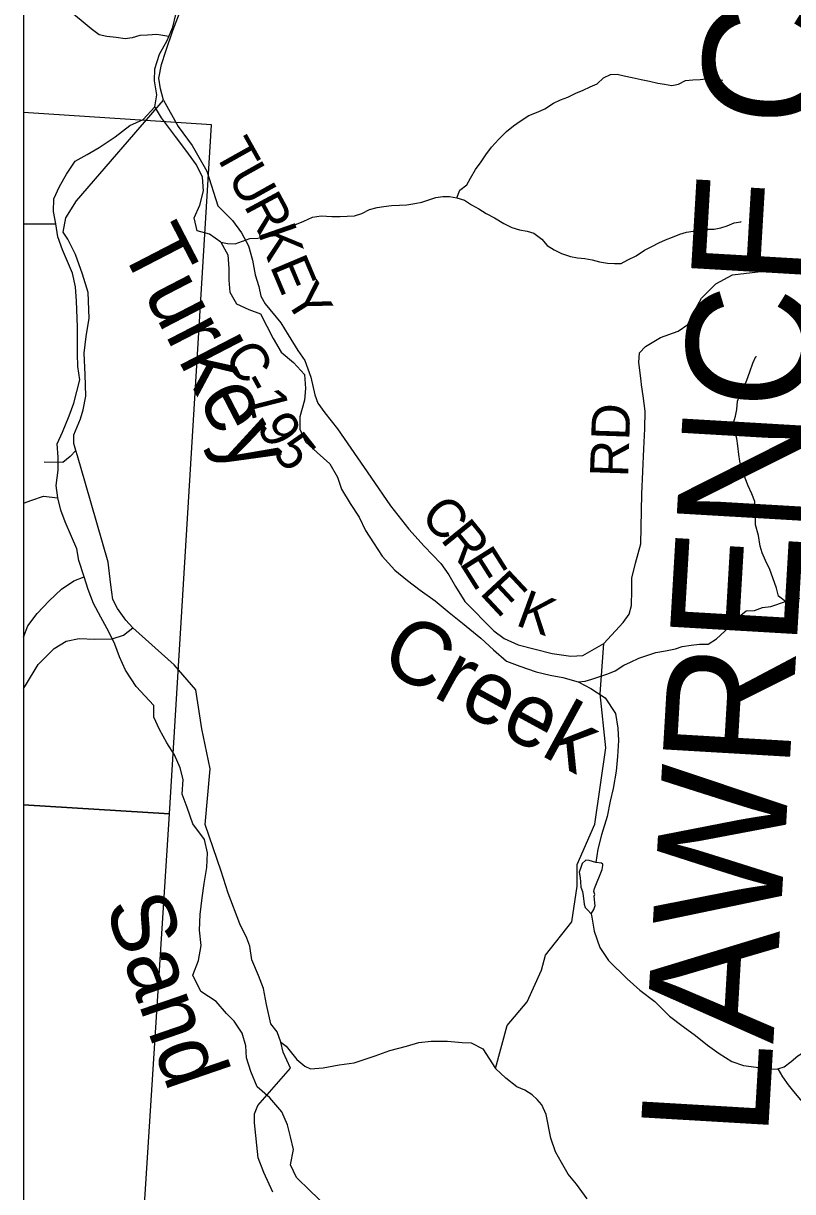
# Model space of a CAD drawing. Extents: x 396.2 to 468.4, y 232.6 to 279.1.
# Drawn here: x 413.851 to 414.996, y 268.036 to 269.775 of the extents above; entities that cross this region are included whole.
import ezdxf

# ---------------------------------------------------------------- set-up
doc = ezdxf.new("R2010")
doc.units = 0
for name, color, linetype in [('Default', 7, 'Continuous'), ('GM_X_County_Road', 7, 'Continuous'), ('GM_X_County_Road_Text', 7, 'Continuous'), ('GM_X_County_Text', 7, 'Continuous'), ('GM_X_Minor_Lake', 7, 'Continuous'), ('GM_X_Minor_River', 7, 'Continuous'), ('GM_X_Minor_River_Text', 7, 'Continuous'), ('GM_X_Township_Road', 7, 'Continuous'), ('SH_Cut_Line', 7, 'Continuous'), ('TX_P_1', 7, 'Continuous')]:
    doc.layers.add(name, color=color, linetype=linetype)

msp = doc.modelspace()

# ---------------------------------------------------------------- linework, layer by layer
at = {"layer": 'Default'}
for points in [[(413.8513, 270.6726), (413.8513, 264.4868), (414.0592, 264.474), (414.3542, 264.4559), (414.8754, 264.4239), (414.9163, 265.108), (414.9927, 266.2714), (414.9935, 266.2891), (414.9982, 266.4735), (415.0293, 266.9964), (415.0582, 267.4588), (415.0934, 268.0402), (415.1765, 269.4523), (415.2459, 270.5284), (415.2492, 270.5871), (414.466, 270.6401), (414.1359, 270.6553), (413.8849, 270.6706)], [(413.8513, 269.6425), (413.8513, 268.6118), (414.0685, 268.5986), (414.131, 269.6239)], [(413.8513, 268.6118), (413.8513, 267.5757), (414.0029, 267.5669), (414.0685, 268.5986)]]:
    msp.add_lwpolyline(points, close=True, dxfattribs=at)
at = {"layer": 'GM_X_County_Road'}
for points in [[(414.0141, 268.8752), (414.0038, 268.8869), (413.9915, 268.9039), (413.9846, 268.9176), (413.9815, 268.9392), (413.9775, 268.973), (413.9439, 269.0902), (413.9319, 269.1312), (413.9294, 269.1395), (413.9265, 269.1497), (413.9264, 269.1627), (413.9365, 269.1866), (413.9402, 269.1996), (413.9443, 269.2201), (413.9433, 269.2524), (413.9416, 269.2843), (413.9449, 269.309), (413.9493, 269.3363), (413.9475, 269.3743), (413.9394, 269.4016), (413.929, 269.4312), (413.9172, 269.4539), (413.9107, 269.4641), (413.9143, 269.4854), (413.9305, 269.5109), (414.06, 269.6608), (414.0553, 269.6775), (414.053, 269.6938), (414.057, 269.714), (414.0633, 269.7337), (414.0738, 269.7646), (414.0869, 269.7992)], [(414.06, 269.6608), (414.0818, 269.6215), (414.1023, 269.5931), (414.124, 269.5552), (414.1405, 269.5036), (414.1625, 269.4817), (414.1758, 269.4635), (414.1862, 269.4442), (414.192, 269.4226), (414.1962, 269.401), (414.2016, 269.3832), (414.2044, 269.3692), (414.2112, 269.3578), (414.2341, 269.3291), (414.2452, 269.3114), (414.2597, 269.2883), (414.2701, 269.2732), (414.2789, 269.2485), (414.2851, 269.222), (414.2893, 269.2095), (414.3, 269.1955), (414.3187, 269.1717), (414.3684, 269.0995), (414.3974, 269.0568), (414.4249, 269.0224), (414.4478, 268.9971), (414.4725, 268.9711), (414.4844, 268.9541), (414.4943, 268.937), (414.5081, 268.9147), (414.5511, 268.8709), (414.5664, 268.8596), (414.5876, 268.8499), (414.6378, 268.8369), (414.6658, 268.8329), (414.6836, 268.8341), (414.7149, 268.8518), (414.7437, 268.8834), (414.7527, 268.8956), (414.7561, 268.9086), (414.7563, 268.9313), (414.7566, 268.9492), (414.7618, 268.9716), (414.77, 269.0001), (414.7715, 269.0741), (414.7742, 269.1417), (414.7759, 269.1713), (414.7766, 269.1979), (414.7733, 269.2209)], [(414.7733, 269.2209), (414.7711, 269.237), (414.7703, 269.243), (414.7667, 269.2703), (414.7678, 269.2848), (414.7768, 269.2943), (414.7991, 269.3077), (414.8253, 269.317), (414.84, 269.3269), (414.849, 269.3452), (414.8603, 269.3662), (414.8814, 269.3872), (414.9063, 269.401), (415.0283, 269.4153), (415.0488, 269.4166), (415.0715, 269.4285), (415.0991, 269.4505), (415.1195, 269.4591), (415.1386, 269.4591), (415.1563, 269.4554), (415.1767, 269.4517)], [(414.2225, 268.0352), (414.2091, 268.0647), (414.2007, 268.0863), (414.1951, 268.1386), (414.195, 268.1519), (414.1999, 268.1641), (414.2489, 268.2196), (414.2377, 268.2434), (414.2344, 268.2586), (414.2291, 268.2738), (414.2197, 268.286), (414.2128, 268.3145), (414.2085, 268.3383), (414.2012, 268.3577), (414.1912, 268.3811), (414.1881, 268.4016), (414.1838, 268.4134), (414.1731, 268.4345), (414.1558, 268.4804), (414.1458, 268.5133), (414.1219, 268.5825), (414.1293, 268.6653), (414.1169, 268.7249), (414.1078, 268.783), (414.0758, 268.8204), (414.0141, 268.8752)]]:
    msp.add_lwpolyline(points, dxfattribs=at)
at = {"layer": 'GM_X_Minor_Lake'}
for points in [[(414.703, 268.5262), (414.6931, 268.5288), (414.6882, 268.5296), (414.6825, 268.5243), (414.681, 268.5201), (414.6784, 268.5114), (414.6795, 268.5031), (414.6802, 268.497), (414.6806, 268.4894), (414.6832, 268.4826), (414.6843, 268.4765), (414.6858, 268.4637), (414.687, 268.4591), (414.6907, 268.4553), (414.6962, 268.4495)], [(414.7122, 268.5156), (414.7134, 268.5213), (414.7134, 268.5237), (414.7113, 268.5249), (414.703, 268.5262)], [(414.6962, 268.4495), (414.7002, 268.4561), (414.7021, 268.4617), (414.7017, 268.4655), (414.701, 268.4716), (414.7006, 268.4758), (414.7014, 268.4784), (414.7002, 268.4826), (414.701, 268.4871), (414.7122, 268.5156)]]:
    msp.add_lwpolyline(points, dxfattribs=at)
at = {"layer": 'GM_X_Minor_River'}
msp.add_line((413.8997, 269.4762), (413.8513, 269.476), dxfattribs=at)
for points in [[(414.0679, 269.7558), (414.05, 269.7588), (414.0359, 269.7576), (414.0246, 269.7569), (414.0132, 269.7534), (414.0026, 269.7519), (413.9894, 269.7542), (413.9754, 269.7557), (413.964, 269.758), (413.9522, 269.7671), (413.9401, 269.7769), (413.9287, 269.7864), (413.9166, 269.7966), (413.9079, 269.8065), (413.8954, 269.8194), (413.8825, 269.8239), (413.8715, 269.8311), (413.8601, 269.8425), (413.8513, 269.8503)], [(414.1536, 268.3014), (414.1381, 268.3188), (414.1155, 268.334), (414.1034, 268.3583), (414.1118, 268.3803), (414.1156, 268.4023), (414.1134, 268.425), (414.1143, 268.4485), (414.1173, 268.4736), (414.1204, 268.4948), (414.1243, 268.5183), (414.1251, 268.5403), (414.1206, 268.56), (414.1032, 268.5836), (414.095, 268.6079), (414.0875, 268.6276), (414.089, 268.6496), (414.0845, 268.6671), (414.0762, 268.6861), (414.0649, 268.7043), (414.0536, 268.724), (414.0454, 268.7423), (414.0454, 268.7597), (414.019, 268.7879), (414.0032, 268.8122), (413.9941, 268.8319), (413.9874, 268.8509), (413.9783, 268.8691), (413.9663, 268.8912), (413.9557, 268.9117), (413.9475, 268.9322), (413.9415, 268.9511), (413.9339, 268.9754), (413.931, 268.9929), (413.9227, 269.0111), (413.9137, 269.0331), (413.9069, 269.0506), (413.9024, 269.0688), (413.9002, 269.087), (413.9033, 269.1098), (413.9033, 269.1295), (413.9018, 269.1492), (413.9094, 269.1667), (413.9193, 269.1909), (413.9262, 269.2098), (413.9308, 269.2273), (413.9354, 269.2447), (413.9324, 269.2644), (413.9317, 269.2834), (413.9318, 269.3236), (413.9304, 269.3615), (413.9289, 269.3828), (413.9244, 269.4033), (413.9094, 269.4382), (413.9026, 269.4572), (413.8996, 269.4769), (413.8959, 269.4951), (413.8967, 269.5141), (413.9051, 269.5323), (413.9157, 269.5505), (413.9286, 269.5702), (413.946, 269.58), (413.9642, 269.5905), (413.9877, 269.6064), (414.0097, 269.623), (414.0294, 269.6321), (414.0469, 269.651), (414.0499, 269.6685), (414.0462, 269.6897), (414.047, 269.7072), (414.0539, 269.7291), (414.0653, 269.7496), (414.0737, 269.7693), (414.0782, 269.7882)], [(414.4962, 269.5154), (414.5007, 269.5267), (414.511, 269.5347), (414.5163, 269.5449), (414.5239, 269.5574), (414.5326, 269.5691), (414.5394, 269.5794), (414.5478, 269.5907), (414.5588, 269.6028), (414.5701, 269.6142), (414.5803, 269.6225), (414.5906, 269.6297), (414.6035, 269.638), (414.6171, 269.6433), (414.6273, 269.6479), (414.6402, 269.6562), (414.6504, 269.6611), (414.6614, 269.6652), (414.6731, 269.6713), (414.6841, 269.6758), (414.6947, 269.6807), (414.7049, 269.6853), (414.7144, 269.694), (414.7246, 269.6989), (414.7345, 269.6993), (414.745, 269.697), (414.7571, 269.6947), (414.7704, 269.6916), (414.7829, 269.6893), (414.795, 269.6859), (414.8052, 269.6844), (414.8158, 269.6825), (414.826, 269.6847), (414.8366, 269.69), (414.8472, 269.6911), (414.8582, 269.6915), (414.8706, 269.693), (414.882, 269.6922), (414.8918, 269.6907)], [(414.1453, 269.4495), (414.1281, 269.4612), (414.11, 269.4665), (414.1055, 269.4855), (414.1139, 269.5044), (414.1192, 269.5257), (414.1178, 269.5462), (414.1087, 269.5644), (414.0929, 269.5864), (414.0778, 269.6069), (414.0567, 269.6343), (414.0477, 269.6494), (414.0469, 269.651)], [(414.1453, 269.4495), (414.1552, 269.4476), (414.1665, 269.4469), (414.1771, 269.451), (414.1881, 269.4548), (414.2002, 269.4555), (414.2135, 269.4578), (414.2263, 269.4593), (414.2369, 269.4672), (414.2472, 269.4733), (414.2578, 269.4763), (414.2684, 269.4805), (414.2812, 269.4865), (414.2941, 269.4884), (414.31, 269.4876), (414.3225, 269.4876), (414.3331, 269.4883), (414.3437, 269.4887), (414.355, 269.4921), (414.366, 269.4978), (414.3777, 269.5011), (414.3876, 269.5023), (414.3989, 269.5041), (414.411, 269.5045), (414.422, 269.5049), (414.4337, 269.5071), (414.444, 269.509), (414.4546, 269.5124), (414.4648, 269.5158), (414.4754, 269.5173), (414.4852, 269.5173), (414.4962, 269.5154), (414.5075, 269.5119), (414.5181, 269.5051), (414.5291, 269.499), (414.54, 269.4922), (414.5521, 269.4857), (414.5661, 269.4774), (414.5782, 269.4713), (414.5895, 269.4679), (414.6009, 269.466), (414.6107, 269.4629), (414.6228, 269.4538), (414.6307, 269.4443), (414.6409, 269.4382), (414.6519, 269.4325), (414.6651, 269.4283), (414.6757, 269.426), (414.6867, 269.4253), (414.6977, 269.423), (414.7083, 269.4203), (414.7204, 269.4184), (414.7306, 269.4176), (414.7408, 269.4176), (414.7506, 269.4229), (414.7631, 269.4293), (414.7753, 269.4376), (414.7862, 269.4429), (414.7968, 269.4486), (414.8067, 269.4528), (414.8169, 269.4569), (414.8279, 269.4611), (414.8377, 269.4645), (414.8479, 269.466), (414.8589, 269.4675), (414.8691, 269.4686), (414.879, 269.469), (414.8888, 269.4708), (414.8986, 269.4739), (414.9089, 269.478), (414.9187, 269.4799), (414.9191, 269.4807)], [(414.1453, 269.4495), (414.1556, 269.4305), (414.1571, 269.4101), (414.1571, 269.3926), (414.1586, 269.3752), (414.1684, 269.3577), (414.1865, 269.3494), (414.2039, 269.3425), (414.2137, 269.3243), (414.2228, 269.3061), (414.2349, 269.2856), (414.253, 269.2705), (414.2696, 269.2523), (414.2711, 269.2318), (414.2696, 269.2143), (414.2627, 269.1893), (414.2627, 269.1711), (414.271, 269.1522), (414.2884, 269.1362), (414.3073, 269.1195), (414.3186, 269.0998), (414.3247, 269.0816), (414.3375, 269.0604), (414.3511, 269.0399), (414.3601, 269.0202), (414.3722, 269.0019), (414.3851, 268.9822), (414.4039, 268.961), (414.4228, 268.9458), (414.4417, 268.9314), (414.4637, 268.9154), (414.4848, 268.898), (414.5045, 268.8821), (414.5317, 268.8601), (414.5506, 268.8426), (414.5702, 268.8259), (414.5899, 268.8183), (414.6141, 268.81), (414.6352, 268.8046), (414.6541, 268.8016), (414.6768, 268.7948), (414.6957, 268.7849), (414.7169, 268.7712), (414.732, 268.7477), (414.7358, 268.7257), (414.7365, 268.7075), (414.735, 268.684), (414.7334, 268.662), (414.7289, 268.6362), (414.7243, 268.6173), (414.7197, 268.5945), (414.7114, 268.5672), (414.7059, 268.5458), (414.703, 268.5262)], [(414.9851, 268.9147), (414.9749, 268.9226), (414.9719, 268.9344), (414.9662, 268.9499), (414.9617, 268.9621), (414.9553, 268.9753), (414.9504, 268.9867), (414.9474, 268.997), (414.9448, 269.0125), (414.9406, 269.0284), (414.9403, 269.0398), (414.9392, 269.0527), (414.9396, 269.0633), (414.9351, 269.0747), (414.9298, 269.0868), (414.9249, 269.0982), (414.9204, 269.1096), (414.9174, 269.1236), (414.9155, 269.1335), (414.9144, 269.146), (414.9129, 269.157), (414.9099, 269.1687), (414.908, 269.1805), (414.9107, 269.1903), (414.9126, 269.2002), (414.9137, 269.2127), (414.9175, 269.2229), (414.9236, 269.2339), (414.9274, 269.2441), (414.932, 269.2566), (414.9365, 269.2691), (414.9411, 269.279), (414.9418, 269.2793)], [(413.8513, 269.0607), (413.8638, 269.0651), (413.8812, 269.0711), (413.9024, 269.0688)], [(413.8513, 268.8612), (413.858, 268.8785), (413.8717, 268.8967), (413.8899, 268.9156), (413.9081, 268.933), (413.9263, 268.9451), (413.9415, 268.9511)], [(414.6768, 268.7948), (414.6872, 268.7961), (414.697, 268.7987), (414.7087, 268.8029), (414.7208, 268.8066), (414.7318, 268.8115), (414.7447, 268.8195), (414.7545, 268.8244), (414.767, 268.8301), (414.7776, 268.8338), (414.7924, 268.8384), (414.8068, 268.841), (414.8215, 268.844), (414.8314, 268.8474), (414.8446, 268.8497), (414.8571, 268.8508), (414.87, 268.8511), (414.8825, 268.8587), (414.895, 268.8701), (414.9048, 268.8807), (414.9162, 268.8924), (414.9268, 268.9007), (414.9389, 268.9011), (414.9507, 268.9056), (414.9631, 268.9071), (414.9851, 268.9147), (414.9949, 268.9173), (415.0063, 268.9195)], [(414.6962, 268.4495), (414.6969, 268.4444), (414.7006, 268.4239), (414.7089, 268.3996), (414.7218, 268.3799), (414.7497, 268.3526), (414.7686, 268.3359), (414.7905, 268.3192), (414.8124, 268.2972), (414.8328, 268.282), (414.851, 268.2684), (414.8691, 268.254), (414.8865, 268.2418), (414.9054, 268.2297), (414.9228, 268.2236), (414.9417, 268.2213), (414.9591, 268.2183), (414.9735, 268.219)], [(414.2993, 268.0169), (414.2782, 268.0374), (414.2578, 268.0571), (414.2487, 268.0761), (414.2533, 268.0988), (414.2487, 268.1178), (414.2442, 268.1352), (414.2359, 268.1549), (414.2178, 268.1754), (414.1989, 268.1921), (414.1898, 268.2149), (414.1831, 268.2354), (414.1823, 268.2528), (414.177, 268.2718), (414.165, 268.29), (414.1536, 268.3014)], [(414.9735, 268.219), (414.9832, 268.2218), (414.9938, 268.2297), (415.0036, 268.2381), (415.0142, 268.2445), (415.0241, 268.2498), (415.0351, 268.2558), (415.046, 268.2634), (415.0559, 268.2736), (415.0661, 268.2778), (415.076, 268.2838), (415.0858, 268.291), (415.0972, 268.2982), (415.1048, 268.3084), (415.1078, 268.3107)], [(414.9735, 268.219), (414.9809, 268.207), (414.9892, 268.1949), (414.9971, 268.185), (415.0077, 268.1725), (415.0167, 268.1619), (415.0243, 268.1524), (415.0299, 268.1421), (415.0364, 268.1323), (415.0466, 268.1209), (415.0537, 268.1114), (415.0571, 268.1), (415.0575, 268.0905), (415.0631, 268.081), (415.073, 268.0723), (415.0828, 268.0632), (415.0926, 268.0533), (415.0926, 268.053)]]:
    msp.add_lwpolyline(points, dxfattribs=at)
at = {"layer": 'GM_X_Township_Road'}
for points in [[(413.9294, 269.1395), (413.9209, 269.1303), (413.9099, 269.1213), (413.8822, 269.1217)], [(413.8513, 268.785), (413.8544, 268.7893), (413.8735, 268.8208), (413.8971, 268.8447), (413.9149, 268.8553), (413.9343, 268.8594), (413.9578, 268.8582), (413.9833, 268.8589), (414.0004, 268.8642), (414.0141, 268.8752)], [(414.69, 268.0252), (414.6741, 268.047), (414.6616, 268.0622), (414.6517, 268.0794), (414.6431, 268.0953), (414.6358, 268.1158), (414.6292, 268.1508), (414.6226, 268.1654), (414.6159, 268.1733), (414.608, 268.1799), (414.5974, 268.1872), (414.5855, 268.1918), (414.569, 268.205), (414.5537, 268.2192), (414.5709, 268.2834), (414.6009, 268.3184), (414.6222, 268.3657), (414.6281, 268.3881), (414.6671, 268.4378), (414.6754, 268.4909), (414.6754, 268.5229), (414.7014, 268.5831), (414.7179, 268.6965), (414.7096, 268.7769), (414.7149, 268.8518)], [(414.2344, 268.2586), (414.2423, 268.2527), (414.2582, 268.2328), (414.2701, 268.2229), (414.2787, 268.2189), (414.2972, 268.2202), (414.321, 268.2249), (414.3435, 268.2275), (414.3746, 268.2381), (414.3964, 268.246), (414.4215, 268.2527), (414.4394, 268.2579), (414.4579, 268.2599), (414.4824, 268.2599), (414.5042, 268.2579), (414.5174, 268.2573), (414.5348, 268.2487), (414.5537, 268.2192)]]:
    msp.add_lwpolyline(points, dxfattribs=at)
at = {"layer": 'SH_Cut_Line'}
msp.add_lwpolyline([(413.8513, 270.6726), (413.8513, 264.2582), (416.1109, 264.2582), (415.3533, 264.289), (414.8684, 264.3083), (414.8754, 264.4239), (414.9163, 265.108), (414.9927, 266.2714), (414.9935, 266.2891), (414.9982, 266.4735), (415.0293, 266.9964), (415.0582, 267.4588), (415.0934, 268.0402), (415.1765, 269.4523), (415.2459, 270.5284), (415.2492, 270.5871), (414.466, 270.6401), (414.1359, 270.6553), (413.8849, 270.6706)], close=True, dxfattribs=at)
at = {"layer": 'TX_P_1'}
msp.add_line((413.8513, 277.8582), (413.8513, 264.2582), dxfattribs=at)

# ---------------------------------------------------------------- texts
at = {"layer": 'GM_X_County_Road_Text'}
for s, height, rotation, p in [('T', 0.0568, 299.2771, (414.1334, 269.5843)), ('U', 0.0568, 299.2736, (414.1542, 269.5472)), ('R', 0.0568, 298.2619, (414.1785, 269.5039)), ('K', 0.0568, 289.2362, (414.1997, 269.4649)), ('E', 0.0568, 292.8953, (414.2175, 269.4141)), ('Y', 0.0568, 302.2078, (414.2387, 269.3661)), ('C', 0.0568, 302.4559, (414.1484, 269.28)), ('-', 0.0568, 298.7631, (414.1729, 269.2414)), ('1', 0.0568, 284.4427, (414.1828, 269.2245)), ('RD', 0.05682, 88.0917, (414.7509, 269.0989)), ('9', 0.0568, 299.3638, (414.1975, 269.1756)), ('5', 0.0568, 308.2121, (414.22, 269.1372)), ('C', 0.0568, 312.159, (414.4398, 269.0407)), ('R', 0.0568, 309.0889, (414.4706, 269.0067)), ('E', 0.0568, 302.2898, (414.499, 268.9719)), ('E', 0.0568, 312.992, (414.5287, 268.9268)), ('K', 0.0568, 339.9227, (414.5818, 268.8798))]:
    msp.add_text(s, height=height, rotation=rotation, dxfattribs=at).set_placement(p)
at = {"layer": 'GM_X_County_Text'}
msp.add_text('LAWRENCE COUNTY', height=0.189394, rotation=86.6482, dxfattribs=at).set_placement((414.9587, 268.1147))
at = {"layer": 'GM_X_Minor_River_Text'}
for s, height, rotation, p in [('Turkey', 0.09469, 297.354, (413.9937, 269.4433)), ('Creek', 0.0947, 331.3529, (414.378, 268.8183)), ('Sand', 0.09469, 288.9679, (413.9722, 268.4619))]:
    msp.add_text(s, height=height, rotation=rotation, dxfattribs=at).set_placement(p)

doc.saveas('drawing.dxf')
